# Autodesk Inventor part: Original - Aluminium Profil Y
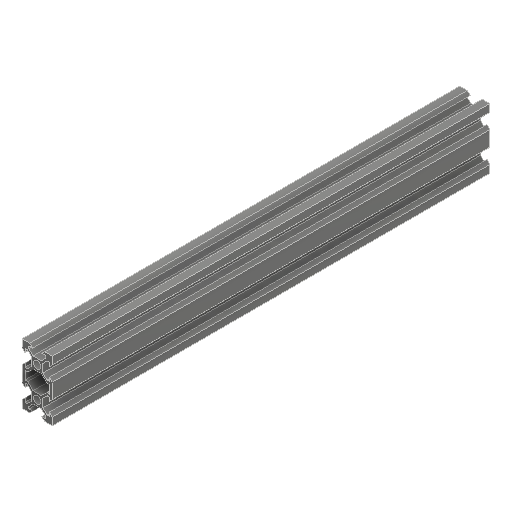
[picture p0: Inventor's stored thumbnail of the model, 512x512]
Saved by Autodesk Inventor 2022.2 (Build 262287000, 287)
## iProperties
Created: 2024-09
Part Number: Original - Aluminium Profil Y
Material: Generico
Document SubType Name: Modeling
Designer: 18907419
Density: 1 g/cm^3
Appearance: Default
Author: 18907419
Revision Number: ANY
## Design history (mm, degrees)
feature "Schnitt-Linear austragen6"
node "Solido1"
